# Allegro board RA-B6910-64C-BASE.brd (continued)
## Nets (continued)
PCIE_COFIG: R259.2 U9.C23
PCIE_REFCLK_N: U9.B25 YJ1.C8_1(TX3-_1)
PCIE_REFCLK_P: U9.B24 YJ1.C7_1(TX3+_1)
PSON1: C78.2 J8.A21(PSON) R2.2 R174.2
PSON2: C90.2 J9.A21(PSON) R1.2 R183.2
PULL_UP_3.3V_PWR1: D2.2(K2) R135.2 R235.1 R236.1
PULL_UP_3.3V_PWR2: D2.1(K1) R138.2 R237.1 R238.1
PWR1_OUTPUT_OK: R127.1 R178.1 U1.117(PT16A*)
PWR1_PRESENT#: C61.1 R131.2 R177.2 U1.114(PT16C)
PWR1_PSON: R2.1 U1.84(PR8C)
PWR1_RSVD: J8.B25(RESERVED)
PWR1_SCL: C73.2 J8.A20(SCL) R236.2 U8.14(SC4)
PWR1_SDA: C75.2 J8.A19(SDA) R235.2 U8.13(SD4)
PWR1_SMB_ALERT#: R135.1 R175.1 U1.112(PT17A*)
PWR2_OUTPUT_OK: R130.1 R187.1 U1.115(PT16B*)
PWR2_PRESENT#: C62.1 R133.2 R186.2 U1.113(PT16D)
PWR2_PSON: R1.1 U1.83(PR8D)
PWR2_RSVD: J9.B25(RESERVED)
PWR2_SCL: C85.2 J9.A20(SCL) R238.2 U8.16(SC5)
PWR2_SDA: C86.2 J9.A19(SDA) R237.2 U8.15(SD5)
PWR2_SMB_ALERT#: R138.1 R184.1 U1.111(PT17B*)
SCL_R: R300.1 R307.1 R309.1 U10.13(SCL_SLAVE)
SDA_R: R302.1 R308.1 R310.1 U10.14(SDA_SLAVE)
SLAVE_INT#: R267.2 R305.1 U10.15(\I\N\T\_\I\N\)
SMI_MDC: R81.2 R257.1 U9.D10
SMI_MDIO: R75.2 R256.1 U9.D7
SW_BOARD_INT#: C141.1 R112.1 U1.40(PB4C/CSSPIN) YJ1.A1_2(SIDEBAND7_2)
SW_BOARD_RST#: C140.1 R20.2 YJ1.D2_2(SIDEBAND6_2)
SW_DCDC_EN: C139.1 R140.2 YJ1.D1_2(SIDEBAND5_2)
SW_RESERVE1: R247.2 R318.1 R321.2
SW_RESERVE2: R248.2 R319.1 R323.2
TO_BMC_INT#: R121.2 R260.2 U9.C37
TO_CPU_INT#: R116.2 R258.2 U9.C20
UART0_SIN: J10.19 R275.1 U9.D1
UART0_SOUT: J10.17 R274.1 U9.B1
USB5V: C106.1 C107.1 C120.1 C121.1 C158.2 J10.21 J10.22 R205.1 U5.6(OUT)
USB_DM: J10.15 U9.D27
USB_DP: J10.14 U9.D28
USB_OC#: R125.2 U9.C29
USB_POWER_EN: R124.2 R209.2 U5.3(EN)
USB_POWER_OC#: R122.1 R208.2 U1.94(PR5A/DQS0)
USB_RX_N: R87.1 U9.A12
USB_RX_P: R69.1 U9.A11
USB_TX_N: U9.D25
USB_TX_P: U9.D24
VR_EN: J11.2 R145.2 R276.1 U9.D30
N17108255: R16.1 U1.125(PT12D/SDA/PCLKC0_0)
N17108932: R4.1 U1.137(PT10C/TDO)
N17120577: R17.1 U1.120(PT15C/JTAGENB)
N17132235: J7.1 R48.2
N17132359: J7.5 R49.2
N17132366: J7.9 R51.2
N17497473: J2.14 R98.1 R278.1 R311.1
N17497957: Q12.1(B) R101.2 R282.2
N17498397: J5.14 R104.1 R284.1 R313.1
N17503631: R54.1 U1.25(PL8C)
N17503838: R327.1 U1.32(PL10A)
N17504179: R6.1 U1.13(PL4C)
N17504817: R326.1 U1.19(PL5A/PCLKT3_1)
N17504991: R31.1 U1.5(PL3A/PCLKT3_2)
N17510509: R20.1 U1.105(PR2C)
N17540351: R89.1 U1.119(PT15D/PROGRAMN)
N17565545: R325.1 U1.3(PL2C/L_GPLLT_IN)
N17614810: J2.1 R96.2
N17614841: J4.1 R99.2
N17614872: J5.1 R102.2
N17614948: J4.3 R100.2
N17614979: J5.3 R103.2
N17615052: J2.3 R97.2
N17711157: J8.B19(A0) R172.1
N17711159: J8.B20(A1) R173.1
N17711235: J9.B22(\\C\R\_\B\U\S\) R185.1
N17711333: J9.B20(A1) R182.1
N17711335: J9.B19(A0) R181.1
N17711436: J8.B22(\\C\R\_\B\U\S\) R176.1
N17755002: J8.A25(PWOK) R178.2
N17758888: J8.A22(\\S\M\B\A\L\E\R\T\) R175.2
N17770839: J9.A25(PWOK) R187.2
N17770842: J9.A22(\\S\M\B\A\L\E\R\T\) R184.2
N17771627: J8.B24(PRESENT) R177.1
N17771650: J9.B24(PRESENT) R186.1
N17785334: C102.2 L2.2 U4.2(SW)
N17785336: R202.1 U4.6(VBST)
N17785348: C103.2 R204.2 R207.1 U4.4(VFB)
N17785528: C102.1 R202.2
N17786050: C91.2 L1.2 U3.2(SW)
N17786052: R192.1 U3.6(VBST)
N17786060: C92.2 R195.2 R201.2 U3.4(VFB)
N17786072: C91.1 R192.2
N17795988: C101.2 Q8.1(B) R199.2 R200.2
N17796014: Q8.3(C) R196.2 R197.1
N17796016: Q7.1(B) R197.2
N17801498: C105.1 L3.1 U5.1(IN)
N17801552: R208.1 U5.4(\\F\A\U\L\T\\)
N17801562: R206.1 U5.5(ILIM)
N17812600: J7.6 R171.1
N17823833: D3.1(ANODE) R194.2
N17824733: D1.1(ANODE) R119.2
N17825329: R124.1 U1.93(PR5B/DQS0N)
N17852949: R157.1 U1.12(PL4B)
N17861782: R220.1 R222.1 U7.7(A0)
N17861792: R223.1 R224.1 U7.6(A1)
N17861802: R225.1 R226.1 U7.5(A2)
N17861847: R219.2 U7.1(SDA)
N17862775: R221.2 U7.3(OS)
N17864736: R241.2 R244.2 U8.1(A0)
N17864738: R243.2 R246.2 U8.21(A2)
N17864740: R242.2 R245.2 U8.2(A1)
N17865867: R239.2 U8.23(SDA)
N17879948: R155.1 U2.7(2Y2)
N17880008: R146.1 U2.18(1Y0)
N17880012: R147.1 U2.16(1Y1)
N17880028: R148.1 U2.14(1Y2)
N17880056: R149.1 U2.12(1Y3)
N17880058: R151.1 U2.3(2Y0)
N17880102: R152.1 U2.5(2Y1)
N17880169: Q4.1(B) R153.2
N17880198: Q4.3(C) R150.2 U2.1(1\O\E\) U2.19(2\O\E\)
N17880220: R156.1 U2.9(2Y3)
N17885472: R125.1 U1.91(PR5D/PCLKC1_0)
N17885725: R116.1 U1.132(PT11B*)
N17885726: R121.1 U1.133(PT11A*)
N17894131: Q3.1(B) R145.1
N17894135: Q3.3(C) R143.1 U1.73(PR10D)
N17894645: R140.1 U1.78(PR9C)
N17894809: R128.1 U1.86(PR8A/DQS1)
N17894927: Q1.1(B) R117.1
N17894931: Q1.3(C) R113.1 U1.104(PR2D)
N17899016: R137.1 U1.60(PB15D)
N17899017: R136.1 U1.59(PB15C)
N17899018: R129.1 U1.54(PB11D)
N17899019: R139.1 U1.61(PB18A)
N17899020: R132.1 U1.57(PB15A)
N17899021: R134.1 U1.58(PB15B)
N17899022: R126.1 U1.52(PB11C)
N17905147: R75.1 R248.1 YJ1.C7_2(TX3+_2)
N17905148: R81.1 R247.1 YJ1.C8_2(TX3-_2)
N17912152: R321.1 U1.128(PT12A*/PCLKT0_1)
N17912154: R323.1 U1.127(PT12B*/PCLKC0_1)
N17933627: C150.2 Q10.1(B) R265.2 R266.2
N17933645: Q10.3(C) R262.2 R263.1
N17933655: Q9.1(B) R263.2
N17959753: R250.1 U1.55(PB11A/PCLKT2_1)
N17959756: R251.1 U1.56(PB11B/PCLKC2_1)
N17959810: R249.1 U1.41(PB4D)
N17988063: R291.2 U10.2(SDA_MST0)
N17988151: R301.2 U10.6(SDA_MST1)
N17988854: R290.2 U10.1(I\N\T\0\)
N17988900: R303.2 U10.7(I\N\T\1\)
N17997808: R267.1 U1.96(PR4C)
N17998511: R269.1 U1.48(PB9D)
N17998908: R272.1 U1.69(PB20B)
N18001007: R298.1 R299.1 U10.12(AD3)
N18001035: R295.1 R296.1 U10.11(AD2)
N18001064: R293.1 R294.1 U10.10(AD1)
N18001098: R289.1 R292.1 U10.9(AD0)
N18008506: J4.14 R101.1 R281.1 R312.1
N18009865: Q11.1(B) R98.2 R279.2
N18010804: Q13.1(B) R104.2 R285.2
N18021498: R58.1 U1.139(PT10A*)
N18217749: R314.1 U1.38(PB4A)
N18217752: R315.1 U1.39(PB4B)
N18217823: R316.1 U1.42(PB6A)
N18217826: R317.1 U1.43(PB6B)
N18217886: R322.1 U1.45(PB6D/SO/SPISO)
N18217888: R320.1 U1.44(PB6C/MCLK/CCLK)
N18217940: R324.1 U1.49(PB9A/PCLKT2_0)
N18225889: Q14.1(B) R331.2 R332.2
N18236302: Q15.1(B) R349.2 R350.2
N18236637: Q16.1(B) R354.2 R355.2
N18282960: J11.1 R356.1

Pads without a net: FD5 1; FD8 1; FD9 1; FD12 1; J1 11 12; J3 11 12; J7 7 8; J8 1 2; J9 1 2; U1 15 17 31 50 62 63 65 67 70 71 77 81 82 85 87 89 92 95 99 100 103 109 110 121 122 129 140; U8 10 11 17 18 19 20

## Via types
v1: diameter 0.457, hole 0.203, TOP to BOTTOM, 2121 vias
v2: diameter 0.457, hole 0.229, TOP to BOTTOM, 123 vias
v3: diameter 0.762, hole 0.381, TOP to BOTTOM, 144 vias
v4: diameter 0.813, hole 0.406, TOP to BOTTOM, 356 vias

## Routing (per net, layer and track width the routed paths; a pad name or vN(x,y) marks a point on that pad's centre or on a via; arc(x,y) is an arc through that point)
12V_LOAD_SHARE: length 403.3
  TOP w0.201: v2(74.62,103.69) 64.25,103.69 61.74,106.19 20.72,106.19 v1(11.42,115.5)
  SIG1 w0.15: v1(11.42,115.5) 11.42,117.78 10.54,118.66 10.54,127.18 J9.B23
  SIG2 w0.16: v2(74.62,103.69) 74.62,111.58 79.86,116.82 85.46,116.82 89.32,120.68 91.82,120.68 95.48,124.35 99.11,124.35 99.74,124.97 103.47,124.97 104.16,125.66 115.18,125.66 120.79,120.06 123.87,120.06 126.35,117.58 142.69,117.58 143.86,118.75 159.24,118.75 162.14,115.85 336.7,115.85 344.8,123.94 368.42,123.94 369.39,124.92 369.39,127.18 J8.B23
GND: length 1652.3
  TOP w0.229: U1.101 120.47,147.58 v1(120.13,147.25) ; v1(131.31,147.25) 130.97,147.58 U1.80 ; U1.116 116.02,143.1 v1(116.32,142.8) ; U1.134 v1(116.32,134.1) ; v1(130.47,128.35) 130.97,127.85 U1.29 ; U1.64 135.32,142.6 134.74,143.18 v1(134.74,143.56) ; U1.18 v1(125.47,125.91) ; U1.8 v1(120.47,128.32) ; U1.124 116.05,139.1 v1(116.32,139.37) ; v1(135.12,137.34) 135.36,137.1 U1.53 ; v1(134.99,133.4) 135.19,133.6 U1.46 ; U1.90 v1(125.97,147.25)
  TOP w0.254: U8.12 v1(92.17,151.95)
  TOP w0.305: U9.A25 v1(166.34,69.42) ; U9.A33 v1(166.34,59.26) ; U9.A30 v1(166.34,63.07) ; U9.B20 v1(165.07,77.04) ; U9.D32 v1(161.26,60.53) ; U9.D8 v1(161.26,92.28) ; U9.B23 v1(165.07,71.96) ; U9.C16 v1(162.53,82.12) ; v1(161.26,87.2) U9.D12 U9.C13 ; U9.D29 v1(161.26,64.34) ; U9.B32 v1(165.07,60.53) ; U9.A39 v1(166.34,51.64) ; U9.C10 v1(162.53,89.74) ; v1(166.34,93.55) U9.A7 v1(165.07,93.55) ; U9.A22 v1(166.34,73.23) ; U9.D20 v1(161.26,77.04) ; U2.10 v1(64.88,90.23) ; U9.A36 v1(166.34,55.45) ; U9.B39 v1(165.07,51.64) ; U9.A4 166.51,96.73 v1(166.74,96.96) ; U9.C33 v1(162.53,59.26) ; v1(165.07,88.47) U9.B11 v1(163.8,88.47) ; U9.D14 v1(162.53,83.39) U9.C15 ; U9.C39 v1(162.53,51.64) ; U9.B34 v1(165.07,57.99) ; v1(99.67,135.08) 99.89,135.3 U10.8 ; U9.B31 v1(165.07,61.8) ; U9.C30 v1(162.53,63.07) ; U9.B29 v1(165.07,64.34) ; U9.D39 v1(161.26,51.64) ; v1(165.07,94.82) U9.B6 v1(163.8,94.82) ; U9.C28 v1(162.53,65.61) ; v1(165.07,96.09) U9.B5 v1(163.8,96.09) ; v1(162.53,70.69) U9.C24 v1(163.8,70.69) ; U9.D35 v1(161.26,56.72) ; U9.A27 v1(165.07,68.15) U9.B26 v1(163.8,69.42) U9.C25 ; v1(165.07,91.01) U9.B9 v1(163.8,91.01) ; U9.D31 v1(161.26,61.8) ; U9.C7 v1(163.8,92.28) U9.B8 v1(165.07,92.28) ; U9.B17 v1(165.07,80.85) ; U9.D26 v1(162.53,68.15) U9.C27 ; U9.D37 v1(162.53,55.45) U9.C36 ; U9.A24 v1(166.34,70.69) ; v1(162.53,78.31) U9.C19 v1(163.8,78.31) ; v1(163.8,74.5) U9.C21 v1(162.53,74.5) ; U9.A13 v1(166.48,85.3) ; U9.A15 v1(165.12,83.34) U9.B14 ; U9.D2 v1(161.26,99.9) ; v1(165.07,87.2) U9.B12 v1(163.8,87.2) ; U9.A28 v1(166.34,65.61) ; U9.A18 v1(166.34,79.58) ; v1(163.8,99.9) U9.B2 v1(165.07,99.9) ; v1(163.8,79.58) U9.C18 v1(162.58,79.53) U9.D17 ; v1(163.75,73.26) 163.17,73.84 U9.C22 v1(162.53,73.23) U9.D23 ; v1(163.8,98.63) U9.B3 v1(165.07,98.63) ; U9.B35 v1(165.07,56.72) ; U9.D9 v1(161.26,91.01) ; U9.A19 v1(166.34,78.31) ; U9.D11 v1(161.26,88.47) ; U9.A16 v1(165.07,82.12) ; U9.C4 v1(162.53,97.36) ; U9.D34 v1(161.26,57.99) ; U9.A10 v1(166.34,89.74) ; U9.D6 v1(161.26,94.82) ; U9.A21 v1(166.34,74.5) ; U9.D3 v1(161.26,98.63) ; U9.D5 v1(161.26,96.09) ; v1(162.55,101.15) U9.C1
  TOP w0.381: v1(369.24,117.96) 369.24,118.64 C77.1 370.13,118.51 v1(370.13,117.96) ; v1(138.67,153.98) 139,153.65 Q3.2 ; U5.2 392.93,29.77 v1(393.18,30.03) ; 10.66,42.47 C131.1 11.01,43.51 11.67,42.85 ; C129.2 v1(379.72,14.7) ; v1(120.54,155.53) 120.23,155.53 119.82,155.93 Q1.2 ; Q13.2 v1(103.98,154.93) ; R127.2 v1(107.69,143.06) ; C134.2 v1(54.5,87.94) ; C73.1 v1(374.83,119.35) ; C17.2 135.24,123.14 135.78,122.61 v1(136.39,122.61) C5.1 ; R282.1 238.12,167.19 v1(238.5,167.56) ; C4.1 140.45,143.31 v1(140.71,143.56) ; R209.1 396.48,30.79 v1(397.37,31.68) ; v1(75.43,100.82) 75.73,100.51 C146.2 ; v1(98.16,140.61) 98.16,140.77 97.91,141.02 R246.1 ; C155.1 C154.1 90.46,129.72 90.15,130.03 v1(89.93,130.03) ; v1(328.41,168.96) 328.18,169.19 R332.1 ; v1(13.12,118.61) 13.6,118.61 C89.1 13.8,119.5 v1(13.12,119.5) ; Q10.2 v1(390.71,45.59) ; C65.2 v1(110.35,141.91) ; C138.2 v1(69.56,89.46) ; v1(118.87,154.84) 118.76,154.84 118.76,154.84 C140.2 ; C136.2 v1(65.65,93.78) ; C8.1 v1(127.24,152.83) ; v1(12.19,118.66) 12.12,118.73 C87.1 ; R180.2 v1(8.5,121.9) ; C149.2 144.42,80.08 v1(144.34,80.01) ; Q4.2 v1(50.35,90.16) ; C78.1 v1(372.54,119.35) ; C10.1 v1(36.69,90.1) ; C19.1 C22.1 v1(110.35,127.94) ; U7.4 v1(147.75,169.12) ; R200.1 v1(413.76,53.9) ; Q16.2 v1(137.53,160.78) ; R355.1 v1(134.48,165.76) ; C147.2 C148.2 75.78,101.53 v1(75.53,101.78) ; v1(102.99,156.82) 102.56,157.25 R285.1 ; Q8.2 409.75,53.01 v1(409.5,53.27) ; C21.1 v1(110.35,133.02) ; v1(124.6,122.68) 124.58,122.71 C48.1 ; C18.2 v1(140.71,149.15) ; C67.1 v1(362.25,118.46) ; R266.1 v1(387.59,45.27) ; R244.1 v1(101.97,155.63) ; C158.1 v1(385.43,26.85) ; C135.2 v1(69.56,85.91) ; C116.2 v1(156.49,173.71) ; C51.1 v1(119.75,122.61) ; C68.1 v1(363.78,118.46) ; Q12.2 v1(233.92,169.02) ; R226.2 v1(158.08,169.22) ; R130.2 v1(110.35,143.06) ; R276.2 v1(144.41,68.63) ; R279.1 137.66,122.48 v1(137.53,122.61) C20.1 ; v1(144.64,125.53) 144.26,125.91 C141.2 ; v4(23.29,117.45) X21.1 ; R295.2 88.89,135.82 v1(87.87,134.8) 88,134.67 R298.2 ; C3.1 v1(140.71,147.12) ; v1(385.43,27.99) R205.2 ; Q15.2 v1(238.3,171.94) ; C7.1 v1(140.71,148.14) ; v1(75.2,99.95) 75.66,99.49 C144.2 C145.2 ; v1(384.65,29.39) R206.2 ; R173.2 v1(373.68,119.35) ; v1(143.63,87.24) R69.2 R87.2 ; C75.1 v1(377.11,119.35) ; C64.2 110.79,139.5 v1(110.35,139.93) ; R289.2 89.02,138.48 v1(88,137.47) 88.38,137.09 R293.2 ; C62.2 v1(110.35,145.47) ; Q11.2 v1(134.67,121.14) ; C61.2 v1(110.35,144.2) ; C130.2 v1(377.43,14.7) ; C2.1 v1(130.9,152.17) ; v1(3.35,118.67) C79.1 C81.1 ; R183.1 v1(17.2,116.69) ; v1(36.69,95.18) R171.2 ; v1(116.32,150.42) 115.81,150.93 C156.2 ; C66.2 113.78,152.87 v1(113.91,153) ; Q7.2 v1(407.86,58.29) ; C6.1 v1(110.35,128.96) ; R172.2 v1(375.97,119.35) ; R174.1 v1(371.4,119.35) ; C23.1 v1(140.71,134.93) ; C50.1 v1(131.05,122.74) ; C16.2 v1(140.71,128.83) ; R222.2 v1(156.36,172.57) ; v1(68.7,84.13) 68.32,84.51 R253.1 ; Q14.2 v1(333.17,169.15) ; C150.1 v1(388.74,45.27) ; R198.2 v1(406.01,57.84) ; C143.2 C142.2 76.6,95.21 v1(77.11,94.69) ; R350.1 233.31,171.86 v1(233.54,171.63) ; R182.2 v1(18.34,119.35) ; C74.1 v1(367.59,118.34) ; C157.1 C49.1 v1(140.58,127.82) ; R45.2 v1(34.15,87.81) ; C86.1 v1(22.15,119.35) ; C9.1 v1(120.39,153.09) ; 49.77,42.85 48.99,43.64 C151.1 48.63,42.34 ; C63.1 v1(54.5,83.11) ; R223.2 v1(156.36,170.53) ; C137.2 v1(65.65,97.84) ; C139.2 v1(134.36,151.21) ; R259.1 v1(144.42,76.51) ; C1.1 v1(114.8,152.96) ; R181.2 v1(21.01,119.35) ; C101.1 v1(413.76,51.11) ; R201.1 v1(394.73,48.06) ; R264.2 v1(394.2,42.98) ; D1.2 v1(113.43,155.37) ; R245.1 v1(98.92,155.63) ; C117.1 v1(99.94,140.64) ; R109.2 v1(116.96,152.96) ; C85.1 v1(19.99,119.35) ; C90.1 v1(17.2,119.35)
  TOP w0.508: U4.1 v1(400.1,56.12) ; v1(410.33,47.68) 410.45,47.55 C97.2 ; v1(93.84,146.36) 99.43,146.36 100.7,145.09 100.7,141.91 v1(100.7,141.91) 100.7,140.28 100.2,139.78 98.96,139.78 96.24,137.06 v1(96.24,131.37) 96.24,123.51 v1(101.6,118.15) 101.6,118.13 104.11,115.62 v1(104.13,115.62) 104.13,115.37 105.02,114.48 106.54,114.48 107.43,115.37 v1(107.43,115.62) 107.43,115.88 v1(104.89,118.42) 98.67,124.64 v1(98.67,125.5) v1(98.67,133.1) 98.67,136.05 99.96,137.34 101.34,137.34 103.24,139.25 103.24,146.36 v1(102.99,146.61) 100.45,149.15 92.83,149.15 90.54,146.87 v1(90.54,142.67) ; R207.2 406.39,51.74 v1(406.77,51.36) ; U3.1 400.36,41.9 v1(399.91,41.46) ; C99.2 414.52,46.92 v1(414.39,47.04) ; 397.25,50.09 397.27,50.12 C108.2 ; C98.2 411.98,47.55 ; C100.1 413.37,47.55 ; C113.2 v1(384.55,55.17) ; Q9.2 v1(393.69,39.42) ; C94.2 v1(399.15,45.77) ; C114.1 v1(384.55,54.03) ; X23.1 v1(415.72,49.27) ; X25.1 v1(404.36,30.15) ; D3.2 v1(416.42,48.31)
  GND1 w0.508: J9.A7 52.46,127.07 ; J9.A7 53.62,125.91 ; J9.A7 51.3,125.91 ; J9.A7 52.46,124.76 ; J4.9 208.34,168.41 ; J4.9 207.28,167.35 ; J4.9 206.22,168.41 ; J2.10 306.18,168.41 ; J2.10 305.12,167.35 ; J2.10 304.06,168.41 ; J8.B9 403.68,129.61 ; J8.B9 404.84,128.45 ; J8.B9 403.68,127.3 ; 113.46,168.41 J5.10 ; J5.10 115.58,168.41 ; J5.10 114.52,167.35 ; J9.A9 47.38,127.07 ; J9.A9 47.38,124.76 ; J9.A9 48.54,125.91 ; 47.38,127.3 J9.B9 ; J9.B9 47.38,129.61 ; J9.B9 48.54,128.45 ; J2.9 303.64,168.41 ; J2.9 301.52,168.41 ; J2.9 302.58,167.35 ; 61.46,125.91 J9.A3 ; J9.A3 63.78,125.91 ; J9.A3 62.62,124.76 ; J9.A3 62.62,127.07 ; J9.B2 65.16,129.61 ; J9.B2 66.32,128.45 ; J9.B2 65.16,127.3 ; J9.B2 64,128.45 ; 382.44,5.75 J10.25 ; J10.25 383.35,4.84 ; J10.25 383.35,6.66 ; J9.A23 11.82,127.07 ; J9.A23 12.98,125.91 ; J9.A23 11.82,124.76 ; J4.11 213.42,168.41 ; J4.11 212.36,169.47 ; J4.11 211.3,168.41 ; J4.11 212.36,167.35 ; J8.B2 422.62,128.45 ; J8.B2 420.3,128.45 ; J8.B2 421.46,127.3 ; J8.B2 421.46,129.61 ; J9.A6 55,127.07 ; J9.A6 56.16,125.91 ; J9.A6 55,124.76 ; J9.A6 53.84,125.91 ; J9.A8 49.92,127.07 ; J9.A8 51.08,125.91 ; J9.A8 48.76,125.91 ; J9.A8 49.92,124.76 ; 66.54,128.45 J9.B1 ; J9.B1 68.86,128.45 ; J9.B1 67.7,127.3 ; J9.B1 67.7,129.61 ; 422.84,125.91 J8.A1 ; J8.A1 424,127.07 ; J8.A1 424,124.76 ; J8.A1 425.16,125.91 ; J9.A4 61.24,125.91 ; J9.A4 58.92,125.91 ; J9.A4 60.08,124.76 ; J9.A4 60.08,127.07 ; J7.10 26.62,98.73 ; J7.10 25.64,99.71 ; J7.10 24.67,98.73 ; J7.10 25.64,97.75 ; 49.92,127.3 J9.B8 ; J9.B8 49.92,129.61 ; J9.B8 51.08,128.45 ; J9.B8 48.76,128.45 ; J9.A5 57.54,127.07 ; J9.A5 58.7,125.91 ; J9.A5 57.54,124.76 ; J9.A5 56.38,125.91 ; J2.11 308.72,168.41 ; J2.11 306.6,168.41 ; J2.11 307.66,167.35 ; J2.11 307.66,169.47 ; 64,125.91 J9.A2 ; J9.A2 65.16,124.76 ; J9.A2 66.32,125.91 ; J9.A2 65.16,127.07 ; 53.84,128.45 J9.B6 ; J9.B6 56.16,128.45 ; J9.B6 55,127.3 ; 418.92,124.76 J8.A3 ; J8.A3 418.92,127.07 ; J8.A3 420.08,125.91 ; J8.A3 417.76,125.91 ; J9.A1 67.7,127.07 ; J9.A1 66.54,125.91 ; J9.A1 67.7,124.76 ; J9.A1 68.86,125.91 ; 421.46,124.76 J8.A2 ; J8.A2 420.3,125.91 ; J8.A2 422.62,125.91 ; J8.A2 421.46,127.07 ; 412.68,128.45 J8.B5 ; J8.B5 415,128.45 ; J8.B5 413.84,127.3 ; 117.06,167.35 J5.11 ; J5.11 118.12,168.41 ; J5.11 116,168.41 ; J5.11 117.06,169.47 ; J8.B1 425.16,128.45 ; J8.B1 424,127.3 ; J8.B1 424,129.61 ; J8.B1 422.84,128.45 ; J10.13 395.35,6.66 ; J10.13 395.35,4.84 ; J10.13 394.44,5.75 ; 62.62,127.3 J9.B3 ; J9.B3 61.46,128.45 ; J9.B3 63.78,128.45 ; 403.68,124.76 J8.A9 ; J8.A9 404.84,125.91 ; J8.A9 403.68,127.07 ; J8.A8 406.22,127.07 ; J8.A8 406.22,124.76 ; J8.A8 407.38,125.91 ; J8.A8 405.06,125.91 ; 385.35,4.84 J10.23 385.35,6.66 ; 25.64,87.59 J7.2 ; J7.2 26.62,88.57 ; J7.2 25.64,89.55 ; J7.2 24.67,88.57 ; 52.46,127.3 J9.B7 ; J9.B7 52.46,129.61 ; J9.B7 53.62,128.45 ; J9.B7 51.3,128.45 ; 416.38,127.3 J8.B4 ; J8.B4 415.22,128.45 ; J8.B4 417.54,128.45 ; J8.B4 416.38,129.61 ; 418.92,127.3 J8.B3 ; J8.B3 417.76,128.45 ; J8.B3 418.92,129.61 ; J8.B3 420.08,128.45 ; J8.A4 416.38,127.07 ; J8.A4 415.22,125.91 ; J8.A4 416.38,124.76 ; J8.A4 417.54,125.91 ; 208.76,168.41 J4.10 ; J4.10 209.82,167.35 ; J4.10 210.88,168.41 ; 412.68,125.91 J8.A5 ; J8.A5 413.84,127.07 ; J8.A5 415,125.91 ; J8.A5 413.84,124.76 ; J9.B4 61.24,128.45 ; J9.B4 58.92,128.45 ; J9.B4 60.08,127.3 ; J8.A7 409.92,125.91 ; J8.A7 407.6,125.91 ; J8.A7 408.76,124.76 ; J8.A7 408.76,127.07 ; J10.4 405.35,2.62 ; 56.38,128.45 J9.B5 ; J9.B5 58.7,128.45 ; J9.B5 57.54,127.3 ; 407.35,6.66 J10.1 408.26,5.75 ; 410.14,128.45 J8.B6 ; J8.B6 411.3,127.3 ; J8.B6 412.46,128.45 ; J10.10 399.35,2.65 ; 393.35,2.84 J10.16 ; J10.16 394.26,3.75 ; J10.16 393.35,4.66 ; J8.B8 407.38,128.45 ; J8.B8 406.22,127.3 ; J8.B8 405.06,128.45 ; 111.98,167.35 J5.9 ; J5.9 113.04,168.41 ; J5.9 110.92,168.41 ; 411.3,124.76 J8.A6 ; J8.A6 410.14,125.91 ; J8.A6 411.3,127.07 ; J8.A6 412.46,125.91 ; 391.35,2.84 J10.18 391.35,4.66 ; J8.B7 409.92,128.45 ; J8.B7 407.6,128.45 ; J8.B7 408.76,127.3 ; 389.35,4.66 J10.20 389.35,2.84 ; J10.7 401.35,6.87
  SIG1 w0.508: v1(110.73,115.62) v1(107.43,115.62) 107.43,115.37 106.54,114.48 105.02,114.48 104.13,115.37 v1(104.13,115.62) 104.13,115.76 106.15,117.78 v1(107.18,117.78) 111.88,117.78 112.77,116.89 v1(123.32,116.89) 127.58,116.89 v1(127.75,116.72) 128.13,116.34 128.13,114.61 127.75,114.23 112.13,114.23 v1(110.73,115.62)
  GND2 w0.508: 56.38,125.91 J9.A5 ; J9.A5 57.54,127.07 ; J9.A5 57.54,124.76 ; J9.A5 58.7,125.91 ; 305.12,167.35 J2.10 ; J2.10 304.06,168.41 ; J2.10 306.18,168.41 ; 58.92,125.91 J9.A4 ; J9.A4 60.08,124.76 ; J9.A4 60.08,127.07 ; J9.A4 61.24,125.91 ; 15.76,62.34 J3.4 ; J3.4 14.24,63.85 ; J3.4 17.27,63.85 ; J3.4 15.76,65.36 ; J8.A7 409.92,125.91 ; J8.A7 408.76,124.76 ; J8.A7 408.76,127.07 ; J8.A7 407.6,125.91 ; J8.A5 415,125.91 ; J8.A5 413.84,124.76 ; J8.A5 413.84,127.07 ; J8.A5 412.68,125.91 ; J9.B2 65.16,129.61 ; J9.B2 65.16,127.3 ; J9.B2 66.32,128.45 ; J9.B2 64,128.45 ; 394.44,5.75 J10.13 ; J10.13 395.35,6.66 ; J10.13 395.35,4.84 ; J1.4 51.76,65.36 ; J1.4 50.24,63.85 ; J1.4 53.27,63.85 ; J1.4 51.76,62.34 ; J10.16 394.26,3.75 ; J10.16 393.35,2.84 ; J10.16 393.35,4.66 ; 113.46,168.41 J5.10 ; J5.10 114.52,167.35 ; J5.10 115.58,168.41 ; J8.A2 422.62,125.91 ; J8.A2 420.3,125.91 ; J8.A2 421.46,124.76 ; J8.A2 421.46,127.07 ; 51.3,125.91 J9.A7 ; J9.A7 53.62,125.91 ; J9.A7 52.46,127.07 ; J9.A7 52.46,124.76 ; 405.06,125.91 J8.A8 ; J8.A8 406.22,127.07 ; J8.A8 406.22,124.76 ; J8.A8 407.38,125.91 ; J9.A9 48.54,125.91 ; J9.A9 47.38,127.07 ; J9.A9 47.38,124.76 ; J8.B6 412.46,128.45 ; J8.B6 410.14,128.45 ; J8.B6 411.3,127.3 ; J9.A23 11.82,127.07 ; J9.A23 12.98,125.91 ; J9.A23 11.82,124.76 ; 55,124.76 J9.A6 ; J9.A6 53.84,125.91 ; J9.A6 56.16,125.91 ; J9.A6 55,127.07 ; 62.62,127.3 J9.B3 ; J9.B3 63.78,128.45 ; J9.B3 61.46,128.45 ; J2.11 308.72,168.41 ; J2.11 307.66,169.47 ; J2.11 307.66,167.35 ; J2.11 306.6,168.41 ; 405.06,128.45 J8.B8 ; J8.B8 406.22,127.3 ; J8.B8 407.38,128.45 ; 211.3,168.41 J4.11 ; J4.11 213.42,168.41 ; J4.11 212.36,167.35 ; J4.11 212.36,169.47 ; J8.A9 403.68,127.07 ; J8.A9 404.84,125.91 ; J8.A9 403.68,124.76 ; J3.5 13.07,63.85 ; J3.5 11.55,62.34 ; J3.5 11.55,65.36 ; J3.5 10.04,63.85 ; J9.A1 68.86,125.91 ; J9.A1 67.7,124.76 ; J9.A1 67.7,127.07 ; J9.A1 66.54,125.91 ; 415.22,128.45 J8.B4 ; J8.B4 416.38,127.3 ; J8.B4 416.38,129.61 ; J8.B4 417.54,128.45 ; 382.44,5.75 J10.25 ; J10.25 383.35,4.84 ; J10.25 383.35,6.66 ; J8.B9 404.84,128.45 ; J8.B9 403.68,127.3 ; J8.B9 403.68,129.61 ; 24.16,62.34 J3.2 ; J3.2 25.67,63.85 ; J3.2 22.64,63.85 ; J3.2 24.16,65.36 ; J9.B5 58.7,128.45 ; J9.B5 56.38,128.45 ; J9.B5 57.54,127.3 ; J3.1 29.87,63.85 ; J3.1 26.84,63.85 ; J3.1 28.36,62.34 ; J3.1 28.36,65.36 ; 64.35,62.34 J1.1 ; J1.1 64.35,65.36 ; J1.1 65.87,63.85 ; J1.1 62.84,63.85 ; J8.B7 409.92,128.45 ; J8.B7 407.6,128.45 ; J8.B7 408.76,127.3 ; J8.B2 421.46,129.61 ; J8.B2 420.3,128.45 ; J8.B2 422.62,128.45 ; J8.B2 421.46,127.3 ; J7.2 25.64,89.55 ; J7.2 24.67,88.57 ; J7.2 26.62,88.57 ; J7.2 25.64,87.59 ; 117.06,167.35 J5.11 ; J5.11 117.06,169.47 ; J5.11 118.12,168.41 ; J5.11 116,168.41 ; 424,124.76 J8.A1 ; J8.A1 425.16,125.91 ; J8.A1 422.84,125.91 ; J8.A1 424,127.07 ; 54.44,63.85 J1.3 ; J1.3 57.47,63.85 ; J1.3 55.95,65.36 ; J1.3 55.95,62.34 ; J1.2 60.16,65.36 ; J1.2 61.67,63.85 ; J1.2 58.64,63.85 ; J1.2 60.16,62.34 ; J10.4 405.35,2.49 ; J1.5 47.55,65.36 ; J1.5 46.04,63.85 ; J1.5 49.07,63.85 ; J1.5 47.55,62.34 ; 52.46,127.3 J9.B7 ; J9.B7 53.62,128.45 ; J9.B7 51.3,128.45 ; J9.B7 52.46,129.61 ; J9.A2 66.32,125.91 ; J9.A2 65.16,124.76 ; J9.A2 65.16,127.07 ; J9.A2 64,125.91 ; 25.64,97.75 J7.10 ; J7.10 26.62,98.73 ; J7.10 25.64,99.71 ; J7.10 24.67,98.73 ; 67.7,127.3 J9.B1 ; J9.B1 66.54,128.45 ; J9.B1 68.86,128.45 ; J9.B1 67.7,129.61 ; 49.92,124.76 J9.A8 ; J9.A8 49.92,127.07 ; J9.A8 48.76,125.91 ; J9.A8 51.08,125.91 ; 368.12,124.76 J8.A23 ; J8.A23 369.28,125.91 ; J8.A23 368.12,127.07 ; J8.B1 424,129.61 ; J8.B1 422.84,128.45 ; J8.B1 424,127.3 ; J8.B1 425.16,128.45 ; 209.82,167.35 J4.10 ; J4.10 210.88,168.41 ; J4.10 208.76,168.41 ; 47.38,127.3 J9.B9 ; J9.B9 48.54,128.45 ; J9.B9 47.38,129.61 ; 413.84,127.3 J8.B5 ; J8.B5 415,128.45 ; J8.B5 412.68,128.45 ; 111.98,167.35 J5.9 ; J5.9 113.04,168.41 ; J5.9 110.92,168.41 ; 55,127.3 J9.B6 ; J9.B6 56.16,128.45 ; J9.B6 53.84,128.45 ; J8.A6 411.3,127.07 ; J8.A6 410.14,125.91 ; J8.A6 412.46,125.91 ; J8.A6 411.3,124.76 ; J9.B4 61.24,128.45 ; J9.B4 58.92,128.45 ; J9.B4 60.08,127.3 ; J8.A3 418.92,127.07 ; J8.A3 417.76,125.91 ; J8.A3 418.92,124.76 ; J8.A3 420.08,125.91 ; J9.B8 51.08,128.45 ; J9.B8 48.76,128.45 ; J9.B8 49.92,129.61 ; J9.B8 49.92,127.3 ; 391.35,2.84 J10.18 391.35,4.66 ; J4.9 208.34,168.41 ; J4.9 206.22,168.41 ; J4.9 207.28,167.35 ; J8.B3 420.08,128.45 ; J8.B3 418.92,129.61 ; J8.B3 417.76,128.45 ; J8.B3 418.92,127.3 ; J8.A4 417.54,125.91 ; J8.A4 416.38,124.76 ; J8.A4 416.38,127.07 ; J8.A4 415.22,125.91 ; 62.62,124.76 J9.A3 ; J9.A3 63.78,125.91 ; J9.A3 62.62,127.07 ; J9.A3 61.46,125.91 ; 19.96,62.34 J3.3 ; J3.3 19.96,65.36 ; J3.3 21.47,63.85 ; J3.3 18.44,63.85 ; 385.35,4.84 J10.23 385.35,6.66 ; J2.9 303.64,168.41 ; J2.9 302.58,167.35 ; J2.9 301.52,168.41 ; 408.26,5.75 J10.1 407.35,6.66 ; J10.10 399.35,2.79 ; 389.35,2.84 J10.20 389.35,4.66 ; J10.7 401.35,7
  SIG2 w0.508: v1(358.85,123.04) v1(347.08,123.04) 345.1,123.04 v1(339.33,117.27) 337.05,114.99 v1(330.44,114.99) v1(268.47,114.99) v1(252.08,114.99) v1(237.35,114.99) v1(220.97,114.99) v1(206.36,114.99) v1(191.25,114.99) v1(180.58,114.99) 161.81,114.99 v1(158.89,117.91) 144.23,117.91 143.04,116.72 v1(135.75,116.72) v1(127.75,116.72) 126.78,116.72 126.23,116.17 126.23,114.73 127.04,113.92 v1(134.74,113.92) 144.2,113.92 145.77,115.5 v1(157.98,115.5) 161.28,112.19 v1(180.84,112.19) v1(191.25,112.19) v1(206.36,112.19) v1(221.22,112.19) v1(237.61,112.19) v1(252.08,112.19) v1(268.34,112.19) v1(330.44,112.19) 338.44,112.19 v1(341.75,115.5) v1(346.95,120.7) v1(359.02,120.7)
  BOTTOM w0.508: J9.A5 57.54,127.07 ; J9.A5 57.54,124.76 ; J9.A5 56.38,125.91 ; J9.A5 58.7,125.91 ; J3.4 17.27,63.85 ; J3.4 15.76,62.34 ; J3.4 14.24,63.85 ; J3.4 15.76,65.36 ; 418.92,127.3 J8.B3 ; J8.B3 418.92,129.61 ; J8.B3 417.76,128.45 ; J8.B3 420.08,128.45 ; 24.67,88.57 J7.2 ; J7.2 25.64,89.55 ; J7.2 26.62,88.57 ; J7.2 25.64,87.59 ; 67.7,127.3 J9.B1 ; J9.B1 67.7,129.61 ; J9.B1 66.54,128.45 ; J9.B1 68.86,128.45 ; J3.2 24.16,65.36 ; J3.2 25.67,63.85 ; J3.2 24.16,62.34 ; J3.2 22.64,63.85 ; 393.35,2.84 J10.16 ; J10.16 394.26,3.75 ; J10.16 393.35,4.66 ; 65.16,127.3 J9.B2 ; J9.B2 64,128.45 ; J9.B2 66.32,128.45 ; J9.B2 65.16,129.61 ; 406.22,124.76 J8.A8 ; J8.A8 406.22,127.07 ; J8.A8 407.38,125.91 ; J8.A8 405.06,125.91 ; 207.28,167.35 J4.9 208.34,168.41 ; 395.35,4.84 J10.13 ; J10.13 394.44,5.75 ; J10.13 395.35,6.66 ; J5.10 115.58,168.41 ; J5.10 113.46,168.41 ; J5.10 114.52,167.35 ; 307.66,167.35 J2.11 ; J2.11 307.66,169.47 ; J2.11 308.72,168.41 ; J2.11 306.6,168.41 ; 55,124.76 J9.A6 ; J9.A6 53.84,125.91 ; J9.A6 55,127.07 ; J9.A6 56.16,125.91 ; J9.B8 51.08,128.45 ; J9.B8 49.92,129.61 ; J9.B8 49.92,127.3 ; J9.B8 48.76,128.45 ; J1.2 61.67,63.85 ; J1.2 58.64,63.85 ; J1.2 60.16,65.36 ; J1.2 60.16,62.34 ; 418.92,124.76 J8.A3 ; J8.A3 420.08,125.91 ; J8.A3 417.76,125.91 ; J8.A3 418.92,127.07 ; 28.36,62.34 J3.1 ; J3.1 29.87,63.85 ; J3.1 26.84,63.85 ; J3.1 28.36,65.36 ; 64.35,62.34 J1.1 ; J1.1 64.35,65.36 ; J1.1 65.87,63.85 ; J1.1 62.84,63.85 ; 420.3,125.91 J8.A2 ; J8.A2 422.62,125.91 ; J8.A2 421.46,127.07 ; J8.A2 421.46,124.76 ; 403.68,127.3 J8.B9 404.84,128.45 ; 61.46,125.91 J9.A3 ; J9.A3 62.62,124.76 ; J9.A3 63.78,125.91 ; J9.A3 62.62,127.07 ; 405.06,128.45 J8.B8 ; J8.B8 407.38,128.45 ; J8.B8 406.22,127.3 ; J10.4 405.35,2.62 ; J7.10 26.62,98.73 ; J7.10 24.67,98.73 ; J7.10 25.64,99.71 ; J7.10 25.64,97.75 ; J3.3 19.96,65.36 ; J3.3 19.96,62.34 ; J3.3 21.47,63.85 ; J3.3 18.44,63.85 ; 383.35,4.84 J10.25 383.35,6.66 ; 113.04,168.41 J5.9 111.98,167.35 ; J9.B7 52.46,129.61 ; J9.B7 53.62,128.45 ; J9.B7 52.46,127.3 ; J9.B7 51.3,128.45 ; 407.6,125.91 J8.A7 ; J8.A7 409.92,125.91 ; J8.A7 408.76,124.76 ; J8.A7 408.76,127.07 ; J9.B6 56.16,128.45 ; J9.B6 55,127.3 ; J9.B6 53.84,128.45 ; 60.08,127.3 J9.B4 ; J9.B4 61.24,128.45 ; J9.B4 58.92,128.45 ; J10.7 401.35,7 ; J2.10 306.18,168.41 ; J2.10 305.12,167.35 ; J2.10 304.06,168.41 ; 410.14,125.91 J8.A6 ; J8.A6 411.3,127.07 ; J8.A6 412.46,125.91 ; J8.A6 411.3,124.76 ; J3.5 13.07,63.85 ; J3.5 11.55,65.36 ; J3.5 11.55,62.34 ; J3.5 10.04,63.85 ; 408.26,5.75 J10.1 407.35,6.66 ; 391.35,4.66 J10.18 391.35,2.84 ; J9.B9 47.38,129.61 ; J9.B9 48.54,128.45 ; J9.B9 47.38,127.3 ; 64,125.91 J9.A2 ; J9.A2 65.16,124.76 ; J9.A2 65.16,127.07 ; J9.A2 66.32,125.91 ; 212.36,167.35 J4.11 ; J4.11 213.42,168.41 ; J4.11 211.3,168.41 ; J4.11 212.36,169.47 ; 422.84,128.45 J8.B1 ; J8.B1 424,129.61 ; J8.B1 425.16,128.45 ; J8.B1 424,127.3 ; 302.58,167.35 J2.9 303.64,168.41 ; 61.46,128.45 J9.B3 ; J9.B3 62.62,127.3 ; J9.B3 63.78,128.45 ; 51.76,62.34 J1.4 ; J1.4 50.24,63.85 ; J1.4 53.27,63.85 ; J1.4 51.76,65.36 ; J9.A23 11.82,127.07 ; J9.A23 11.82,124.76 ; J9.A23 12.98,125.91 ; 407.6,128.45 J8.B7 ; J8.B7 409.92,128.45 ; J8.B7 408.76,127.3 ; J5.11 117.06,169.47 ; J5.11 118.12,168.41 ; J5.11 117.06,167.35 ; J5.11 116,168.41 ; J9.A1 67.7,127.07 ; J9.A1 67.7,124.76 ; J9.A1 66.54,125.91 ; J9.A1 68.86,125.91 ; 46.04,63.85 J1.5 ; J1.5 47.55,62.34 ; J1.5 47.55,65.36 ; J1.5 49.07,63.85 ; 51.3,125.91 J9.A7 ; J9.A7 53.62,125.91 ; J9.A7 52.46,124.76 ; J9.A7 52.46,127.07 ; J1.3 57.47,63.85 ; J1.3 55.95,62.34 ; J1.3 55.95,65.36 ; J1.3 54.44,63.85 ; 416.38,124.76 J8.A4 ; J8.A4 416.38,127.07 ; J8.A4 417.54,125.91 ; J8.A4 415.22,125.91 ; 368.12,124.76 J8.A23 ; J8.A23 368.12,127.07 ; J8.A23 369.28,125.91 ; J9.A8 51.08,125.91 ; J9.A8 49.92,127.07 ; J9.A8 48.76,125.91 ; J9.A8 49.92,124.76 ; 389.35,4.66 J10.20 389.35,2.84 ; 385.35,4.84 J10.23 385.35,6.66 ; 411.3,127.3 J8.B6 ; J8.B6 412.46,128.45 ; J8.B6 410.14,128.45 ; J8.B5 415,128.45 ; J8.B5 412.68,128.45 ; J8.B5 413.84,127.3 ; J9.A9 48.54,125.91 ; J9.A9 47.38,124.76 ; J9.A9 47.38,127.07 ; 421.46,127.3 J8.B2 ; J8.B2 422.62,128.45 ; J8.B2 420.3,128.45 ; J8.B2 421.46,129.61 ; J8.A1 424,127.07 ; J8.A1 425.16,125.91 ; J8.A1 422.84,125.91 ; J8.A1 424,124.76 ; J8.B4 417.54,128.45 ; J8.B4 416.38,129.61 ; J8.B4 416.38,127.3 ; J8.B4 415.22,128.45 ; J9.A4 60.08,127.07 ; J9.A4 61.24,125.91 ; J9.A4 60.08,124.76 ; J9.A4 58.92,125.91 ; J8.A9 404.84,125.91 ; J8.A9 403.68,127.07 ; J8.A9 403.68,124.76 ; J8.A5 415,125.91 ; J8.A5 412.68,125.91 ; J8.A5 413.84,127.07 ; J8.A5 413.84,124.76 ; J4.10 210.88,168.41 ; J4.10 209.82,167.35 ; J4.10 208.76,168.41 ; 57.54,127.3 J9.B5 ; J9.B5 58.7,128.45 ; J9.B5 56.38,128.45 ; J10.10 399.35,2.54
  vias: v1(1.26,136.07) v1(1.26,134.8) v1(1.26,133.53) v1(1.26,132.26) v1(1.26,130.99) v1(1.26,129.72) v1(1.26,128.45) v1(1.26,127.18) v1(1.26,125.91) v1(1.26,124.64) v1(1.26,123.24) v1(1.26,121.97) v1(1.26,120.7) v1(1.26,119.43) v1(1.26,118.16) v1(1.26,116.89) v1(1.26,115.62) v1(1.26,113.08) v1(1.26,111.81) v1(1.26,110.54) v1(1.26,109.27) v1(1.26,108) v1(1.26,106.73) v1(1.26,105.46) v1(1.26,104.19) v1(1.26,102.92) v1(1.26,101.65) v1(1.26,100.38) v1(1.26,99.11) v1(1.26,97.84) v1(1.26,96.57) v1(1.26,95.18) v1(1.26,93.91) v1(1.26,92.64) v1(1.26,91.37) v1(1.26,90.1) v1(1.26,88.83) v1(1.26,87.56) v1(1.26,86.29) v1(1.26,85.02) v1(1.26,83.75) v1(1.26,82.48) v1(1.26,81.21) v1(1.26,79.94) v1(1.26,78.67) v1(1.26,77.4) v1(1.26,76) v1(1.26,74.73) v1(1.26,73.46) v1(1.26,72.19) v1(1.26,70.92) v1(1.26,69.65) v1(1.26,68.38) v1(1.26,67.11) v1(1.26,65.84) v1(1.26,64.57) v1(1.26,63.3) v1(1.26,62.03) v1(1.26,60.76) v1(1.26,59.49) v1(1.26,58.22) v1(1.26,56.95) v1(1.26,55.68) v1(1.26,54.41) v1(1.26,53.14) v1(1.26,51.87) v1(1.26,50.6) v1(1.26,49.33) v1(1.26,48.06) v1(1.26,46.79) v1(1.26,45.52) v1(1.26,44.25) v1(1.26,42.98) v1(1.26,41.71) v1(1.26,40.44) v1(1.26,39.17) v1(1.26,37.9) v1(1.26,36.63) v1(1.26,35.36) v1(1.26,34.09) v1(1.26,32.82) v1(1.26,31.55) v1(1.26,30.28) v1(1.26,28.88) v1(1.26,27.61) v1(1.26,26.34) v1(1.26,25.07) v1(1.26,23.8) v1(1.26,22.53) v1(1.26,21.26) v1(1.26,19.99) v1(1.26,18.72) v1(1.26,17.45) v1(1.26,16.18) v1(1.26,14.91) v1(1.26,13.64) v1(1.26,12.37) v1(1.26,11.1) v1(1.26,9.83) v1(1.26,8.56) v1(1.26,7.29) v1(1.26,6.02) v1(1.26,4.75) v1(1.26,3.48) v1(1.26,2.21) v1(2.4,1.32) v1(3.67,1.32) v1(4.94,1.32) v1(6.21,1.32) v1(7.48,1.32) v1(8.75,1.32) v1(11.29,1.32) v1(12.56,1.32) v1(12.82,98.86) v1(12.94,105.46) v1(12.94,91.11) v1(13.83,1.32) v1(15.1,1.32) v1(15.36,24.31) v1(16.37,1.32) v1(17.64,1.32) v1(18.91,1.32) v1(20.18,1.32) v1(21.45,1.32) v1(22.72,1.32) v1(23.99,1.32) v1(25.26,13.77) v1(25.26,1.32) v1(25.52,24.31) v1(26.53,1.32) v1(27.8,1.32) v1(29.07,1.32) v1(30.34,1.32) v1(31.61,1.32) v1(33.01,1.32) v1(34.03,74.09) v1(34.15,79.17) v1(34.28,1.32) v1(35.42,13.77) v1(35.55,1.32) v1(35.68,24.31) v1(36.69,104.57) v1(36.82,99.75) v1(36.82,1.32) v1(38.09,1.32) v1(39.36,1.32) v1(40.63,1.32) v1(41.9,1.32) v1(43.17,1.32) v1(44.44,1.32) v1(45.58,13.64) v1(45.71,1.32) v1(45.84,24.18) v1(46.98,1.32) v1(48.25,1.32) v1(49.52,1.32) v1(50.28,96.7) v1(50.79,1.32) v1(52.06,1.32) v1(53.33,1.32) v1(54.6,1.32) v1(55.36,78.03) v1(55.35,75.23) v1(55.74,13.64) v1(55.87,1.32) v1(56,24.18) v1(57.14,1.32) v1(58.41,1.32) v1(59.68,1.32) v1(60.95,1.32) v1(62.22,1.32) v1(63.49,1.32) v1(64.51,101.91) v1(64.56,98.35) v1(64.76,1.32) v1(65.52,112.07) v1(65.47,107.88) v1(66.03,1.32) v1(67.3,1.32) v1(68.06,96.57) v1(68.06,13.01) v1(68.32,33.58) v1(68.32,23.55) v1(68.57,1.32) v1(69.84,93.65) v1(69.84,1.32) v1(70.48,88.58) v1(70.6,128.45) v1(71.11,1.32) v1(71.82,144.46) v1(72,89.21) v1(72.38,1.32) v1(73.09,144.46) v1(73.65,1.32) v1(74.36,144.46) v1(74.65,102.8) v1(74.92,1.32) v1(75.63,144.46) v1(76.19,1.32) v1(76.9,144.46) v1(77.46,1.32) v1(78.17,144.46) v1(78.22,13.01) v1(78.48,33.58) v1(78.48,23.55) v1(78.73,1.32) v1(79.49,144.96) v1(80,1.32) v1(80.76,144.96) v1(81.27,1.32) v1(82.03,145.6) v1(82.54,1.32) v1(83.3,185.73) v1(83.3,184.46) v1(83.3,183.19) v1(83.3,181.92) v1(83.3,180.65) v1(83.3,179.38) v1(83.3,169.22) v1(83.3,167.82) v1(83.3,166.55) v1(83.3,165.28) v1(83.3,164.01) v1(83.3,162.74) v1(83.3,161.47) v1(83.3,160.2) v1(83.3,158.93) v1(83.3,157.66) v1(83.3,156.39) v1(83.3,155.12) v1(83.3,153.85) v1(83.3,152.58) v1(83.3,151.31) v1(83.3,150.04) v1(83.3,148.77) v1(83.3,147.5) v1(83.3,146.23) v1(83.81,1.32) v1(83.94,178.11) v1(83.94,176.84) v1(83.94,175.57) v1(83.94,174.3) v1(83.94,173.03) v1(83.94,171.76) v1(83.94,170.49) v1(84.7,186.62) v1(85.08,1.32) v1(85.73,133.1) v1(85.97,186.62) v1(86.35,1.32) v1(87.24,186.62) v1(87.24,80.95) v1(87.62,1.32) v1(88.18,87.45) v1(88.38,13.01) v1(88.59,126.85) v1(88.64,33.58) v1(88.64,23.55) v1(88.89,1.32) v1(89.49,140.43) v1(89.5,80.9) v1(89.79,131.6) v1(90.16,1.32) v1(90.29,155.5) v1(91.05,186.62) v1(91.22,104.07) v1(91.22,100.27) v1(91.22,96.47) v1(91.22,92.67) v1(91.43,1.32) v1(92.19,106.67) v1(92.19,102.87) v1(92.19,99.07) v1(92.19,95.27) v1(92.32,186.62) v1(92.7,1.32) v1(93.26,133.66) v1(93.47,104.07) v1(93.47,100.27) v1(93.47,96.47) v1(93.59,186.62) v1(93.97,1.32) v1(94.1,83.11) v1(94.43,159.13) v1(94.44,106.67) v1(94.44,102.87) v1(94.44,99.07) v1(94.72,126.71) v1(94.86,186.62) v1(95.24,1.32) v1(95.83,159.05) v1(96.13,186.62) v1(96.51,1.32) v1(97.02,143.31) v1(97.08,152.02) v1(97.4,186.62) v1(97.78,1.32) v1(98.54,12.88) v1(98.67,152.58) v1(98.67,33.71) v1(98.8,186.62) v1(98.8,23.42) v1(99.05,1.32) v1(100.07,186.62) v1(100.32,1.32) v1(101.34,186.62) v1(101.59,1.32) v1(101.72,128.04) v1(102.61,186.62) v1(102.86,1.32) v1(102.99,170.87) v1(102.99,168.58) v1(102.99,166.3) v1(103.22,151.95) v1(103.22,104.07) v1(103.22,100.27) v1(103.22,96.47) v1(103.22,92.67) v1(103.71,129.28) v1(103.88,186.62) v1(103.88,170.87) v1(103.88,168.58) v1(103.88,166.3) v1(104.08,147.04) v1(104.11,138.7) v1(104.13,1.32) v1(104.19,106.67) v1(104.19,102.87) v1(104.19,99.07) v1(104.19,95.27) v1(105.15,186.62) v1(105.17,135.6) v1(105.4,1.32) v1(105.47,104.07) v1(105.47,100.27) v1(105.47,96.47) v1(105.66,125.2) v1(106.16,127.56) v1(106.42,186.62) v1(106.44,106.67) v1(106.44,99.07) v1(106.42,61.65) v1(106.45,121.92) v1(106.67,72.19) v1(106.67,1.32) v1(107.69,186.62) v1(107.94,1.32) v1(108.08,129.69) v1(108.57,185.09) v1(108.57,133.22) v1(108.7,12.88) v1(108.83,153.47) v1(108.96,186.62) v1(108.96,33.58) v1(108.96,23.42) v1(109.87,126.8) v1(109.97,121.93) v1(110.23,186.62) v1(111.5,186.62) v1(112.77,186.62) v1(112.87,134.84) v1(113.02,1.32) v1(114.04,186.62) v1(114.32,123.58) v1(114.29,1.32) v1(115.31,186.62) v1(115.56,1.32) v1(116.3,126.14) v1(116.58,186.62) v1(116.58,61.65) v1(116.83,72.19) v1(116.83,1.32) v1(117.85,186.62) v1(118.1,130.36) v1(118.1,1.32) v1(118.73,185.09) v1(118.73,174.93) v1(118.86,12.88) v1(119.12,186.62) v1(119.12,33.58) v1(119.12,23.42) v1(119.37,1.32) v1(120.39,186.62) v1(120.64,1.32) v1(121.27,132.77) v1(121.66,186.62) v1(121.91,1.32) v1(122.05,118.11) v1(122.93,186.62) v1(123.18,1.32) v1(123.32,155.07) v1(123.43,118.16) v1(124.2,186.62) v1(124.45,1.32) v1(124.98,128.4) v1(125.47,186.62) v1(125.72,1.32) v1(126.23,159.18) v1(126.74,186.62) v1(126.75,131.7) v1(126.74,61.52) v1(126.99,72.06) v1(126.99,1.32) v1(128.01,186.62) v1(128.26,1.32) v1(128.89,185.09) v1(128.89,174.93) v1(129.02,12.88) v1(129.28,186.62) v1(129.28,33.58) v1(129.28,23.42) v1(129.53,1.32) v1(130.17,122.68) v1(130.55,186.62) v1(130.8,1.32) v1(131.82,186.62) v1(132.09,108.09) v1(132.07,1.32) v1(132.19,106.7) v1(132.88,129.24) v1(133.09,186.62) v1(133.34,1.32) v1(133.66,103.66) v1(134.36,186.62) v1(134.35,152.82) v1(134.61,1.32) v1(135.63,186.62) v1(135.88,1.32) v1(136.9,186.62) v1(137.15,1.32) v1(137.85,107.56) v1(138.17,186.62) v1(138.42,1.32) v1(139.05,185.09) v1(139.05,174.93) v1(139.18,12.88) v1(139.44,186.62) v1(139.44,33.58) v1(139.44,23.42) v1(139.69,1.32) v1(140.71,186.62) v1(140.96,1.32) v1(141.17,139.95) v1(141.98,186.62) v1(142.23,1.32) v1(142.36,110.54) v1(142.61,89.59) v1(143.25,186.62) v1(143.5,1.32) v1(143.64,169.54) v1(143.79,171.7) v1(143.75,146.74) v1(144.52,186.62) v1(144.77,1.32) v1(145.02,141.28) v1(145.79,186.62) v1(145.97,76.66) v1(146.04,1.32) v1(146.29,68.63) v1(146.42,65.28) v1(146.53,127.42) v1(146.93,145.34) v1(147.06,186.62) v1(147.31,1.32) v1(147.57,87.5) v1(147.57,85.85) v1(148.33,186.62) v1(149.21,185.09) v1(149.21,174.93) v1(149.6,186.62) v1(149.6,33.58) v1(149.6,23.42) v1(150.87,186.62) v1(150.95,89.66) v1(152.14,186.62) v1(153.41,186.62) v1(154.02,89.66) v1(154.55,82.6) v1(154.68,186.62) v1(155.95,186.62) v1(156.96,79.17) v1(157.22,186.62) v1(158.49,186.62) v1(158.49,81.84) v1(158.74,1.32) v1(158.99,57.77) v1(159.37,185.09) v1(159.37,174.93) v1(159.63,157.28) v1(159.76,186.62) v1(159.76,33.58) v1(159.76,23.42) v1(160.01,1.32) v1(160.24,83.39) v1(160.24,82.12) v1(160.24,79.58) v1(160.24,78.31) v1(160.26,64.82) v1(161.03,186.62) v1(161.28,1.32) v1(162.3,186.62) v1(162.55,1.32) v1(163.57,186.62) v1(163.82,1.32) v1(164.84,186.62) v1(165.09,1.32) v1(165.22,162.36) v1(165.34,157.15) v1(166.11,186.62) v1(166.36,1.32) v1(166.72,124.88) v1(167.38,186.62) v1(167.36,96.09) v1(167.36,94.82) v1(167.36,92.28) v1(167.36,91.01) v1(167.36,88.47) v1(167.36,87.2) v1(167.37,83.05) v1(167.36,61.8) v1(167.36,60.53) v1(167.63,1.32) v1(167.99,124.87) v1(168.65,186.62) v1(168.9,1.32) v1(169.38,124.83) v1(169.38,123.05) v1(169.53,185.09) v1(169.53,174.93) v1(169.92,186.62) v1(169.92,33.58) v1(169.92,23.42) v1(170.17,1.32) v1(170.93,56.31) v1(171.19,186.62) v1(171.44,1.32) v1(172.2,162.49) v1(172.33,157.28) v1(172.46,186.62) v1(172.71,1.32) v1(173.04,121.34) v1(173.22,125.02) v1(173.73,186.62) v1(173.85,56.31) v1(173.98,1.32) v1(174.74,56.31) v1(175,186.62) v1(175.25,1.32) v1(175.88,99.82) v1(175.88,98.73) v1(175.96,123.98) v1(176.01,121.31) v1(176.27,186.62) v1(176.52,1.32) v1(177.38,101.53) v1(177.41,69.65) v1(177.54,186.62) v1(177.79,1.32) v1(178.39,101.53) v1(178.81,186.62) v1(178.93,162.49) v1(179.06,157.28) v1(179.06,1.32) v1(179.69,185.35) v1(179.69,175.19) v1(179.82,131.88) v1(180.08,186.62) v1(180.08,33.58) v1(180.08,23.42) v1(180.33,1.32) v1(180.46,106.1) v1(180.46,101.65) v1(180.46,96.57) v1(180.46,91.49) v1(180.46,86.41) v1(180.46,81.33) v1(180.46,76.25) v1(181.35,186.62) v1(181.6,1.32) v1(181.98,140.77) v1(182.62,186.62) v1(182.87,1.32) v1(183.89,186.62) v1(184.14,1.32) v1(185.41,1.32) v1(186.68,1.32) v1(187.7,186.62) v1(187.95,1.32) v1(188.97,186.62) v1(189.22,1.32) v1(189.85,185.35) v1(189.85,175.19) v1(190.24,186.62) v1(190.49,1.32) v1(191.51,186.62) v1(191.76,1.32) v1(192.27,23.42) v1(192.39,34.09) v1(192.39,13.77) v1(192.65,140.77) v1(192.78,186.62) v1(193.03,1.32) v1(194.05,186.62) v1(194.3,1.32) v1(195.32,186.62) v1(195.57,1.32) v1(196.33,156.39) v1(196.59,186.62) v1(196.59,159.69) v1(196.84,1.32) v1(197.86,186.62) v1(198.11,1.32) v1(199.13,186.62) v1(199.38,1.32) v1(199.51,130.61) v1(199.51,120.45) v1(200.01,185.35) v1(200.01,175.19) v1(200.4,186.62) v1(200.65,1.32) v1(201.67,186.62) v1(201.92,1.32) v1(202.05,140.77) v1(202.55,105.21) v1(202.55,95.05) v1(202.55,84.89) v1(202.55,74.73) v1(202.55,64.57) v1(202.55,44.25) v1(202.55,34.09) v1(202.55,24.06) v1(202.55,13.77) v1(202.94,186.62) v1(203.19,1.32) v1(204.21,186.62) v1(204.46,1.32) v1(205.48,186.62) v1(205.73,1.32) v1(206.54,161.67) v1(206.75,186.62) v1(207,1.32) v1(208.02,186.62) v1(208.27,1.32) v1(209.29,186.62) v1(209.54,1.32) v1(210.17,185.35) v1(210.17,175.19) v1(210.17,140.77) v1(210.17,130.61) v1(210.17,120.45) v1(210.56,186.62) v1(210.64,161.42) v1(210.81,1.32) v1(211.83,186.62) v1(212.08,1.32) v1(212.33,156.39) v1(212.59,159.06) v1(212.71,105.21) v1(212.71,95.05) v1(212.71,84.89) v1(212.71,74.73) v1(212.71,54.41) v1(212.71,44.25) v1(212.71,34.09) v1(212.71,24.06) v1(212.71,13.77) v1(213.1,186.62) v1(213.35,1.32) v1(214.37,186.62) v1(214.62,1.32) v1(215.64,186.62) v1(215.89,1.32) v1(216.91,186.62) v1(217.16,1.32) v1(218.18,186.62) v1(218.43,1.32) v1(218.94,158.93) v1(219.45,186.62) v1(219.7,1.32) v1(220.33,185.35) v1(220.33,175.19) v1(220.33,140.77) v1(220.33,130.61) v1(220.33,120.45) v1(220.72,186.62) v1(220.72,151.06) v1(220.97,1.32) v1(221.99,186.62) v1(222.24,1.32) v1(222.87,105.21) v1(222.87,95.05) v1(222.87,84.89) v1(222.87,64.57) v1(222.87,54.41) v1(222.87,44.25) v1(222.87,34.09) v1(222.87,24.06) v1(222.87,13.77) v1(223.26,186.62) v1(223.51,1.32) v1(224.53,186.62) v1(224.78,1.32) v1(225.8,186.62) v1(226.05,1.32) v1(227.07,186.62) v1(227.32,1.32) v1(228.34,186.62) v1(228.59,1.32) v1(229.61,186.62) v1(229.86,1.32) v1(230.49,185.35) v1(230.49,175.19) v1(230.49,140.77) v1(230.49,130.61) v1(230.49,120.45) v1(230.88,186.62) v1(230.88,151.06) v1(231.13,1.32) v1(232.15,186.62) v1(232.4,1.32) v1(232.91,34.22) v1(233.03,105.21) v1(233.03,95.05) v1(233.03,74.73) v1(233.03,64.57) v1(233.03,54.41) v1(233.03,44.25) v1(233.03,23.93) v1(233.03,13.77) v1(233.42,186.62) v1(233.67,1.32) v1(234.69,186.62) v1(234.94,1.32) v1(235.96,186.62) v1(236.21,1.32) v1(237.23,186.62) v1(237.48,1.32) v1(238.5,186.62) v1(238.75,1.32) v1(239.77,186.62) v1(240.02,1.32) v1(240.65,185.35) v1(240.65,175.19) v1(240.65,140.77) v1(240.65,130.61) v1(241.04,186.62) v1(241.04,151.06) v1(241.29,1.32) v1(242.31,186.62) v1(242.56,1.32) v1(242.94,44.38) v1(243.19,105.21) v1(243.19,84.89) v1(243.19,74.73) v1(243.19,64.57) v1(243.19,54.41) v1(243.19,34.09) v1(243.19,23.93) v1(243.19,13.77) v1(243.58,186.62) v1(243.83,1.32) v1(245.1,1.32) v1(246.12,186.62) v1(246.37,1.32) v1(247.39,186.62) v1(247.64,1.32) v1(248.66,186.62) v1(248.91,1.32) v1(249.67,179.76) v1(249.93,186.62) v1(250.18,1.32) v1(250.81,140.77) v1(250.81,130.61) v1(250.81,120.45) v1(251.2,151.06) v1(251.45,1.32) v1(251.83,160.07) v1(252.34,186.62) v1(252.72,1.32) v1(253.35,105.21) v1(253.35,95.05) v1(253.35,84.89) v1(253.35,74.73) v1(253.35,64.57) v1(253.35,54.41) v1(253.35,44.25) v1(253.35,34.09) v1(253.35,23.93) v1(253.35,13.77) v1(253.61,186.62) v1(253.61,184.33) v1(253.61,174.17) v1(253.99,1.32) v1(254.88,186.62) v1(255.26,1.32) v1(256.15,186.62) v1(256.53,1.32) v1(257.42,186.62) v1(257.8,1.32) v1(258.69,186.62) v1(259.07,1.32) v1(259.96,186.62) v1(260.34,1.32) v1(260.97,140.77) v1(260.97,130.61) v1(260.97,120.45) v1(261.23,186.62) v1(261.36,151.06) v1(261.61,1.32) v1(261.99,160.07) v1(262.63,186.62) v1(262.88,1.32) v1(263.26,64.7) v1(263.51,105.21) v1(263.51,95.05) v1(263.51,84.89) v1(263.51,74.73) v1(263.51,54.41) v1(263.51,44.25) v1(263.51,34.09) v1(263.51,23.93) v1(263.51,13.77) v1(263.77,184.33) v1(263.77,174.17) v1(263.9,186.62) v1(264.15,1.32) v1(265.17,186.62) v1(265.42,1.32) v1(266.44,186.62) v1(266.69,1.32) v1(267.71,186.62) v1(267.96,1.32) v1(268.98,186.62) v1(269.23,1.32) v1(270.25,186.62) v1(270.5,1.32) v1(271.13,140.77) v1(271.13,130.61) v1(271.52,186.62) v1(271.52,151.06) v1(271.77,1.32) v1(272.15,160.07) v1(272.79,186.62) v1(273.04,1.32) v1(273.67,105.21) v1(273.67,95.05) v1(273.67,84.89) v1(273.67,64.57) v1(273.67,54.41) v1(273.67,44.25) v1(273.67,34.09) v1(273.67,23.93) v1(273.67,13.77) v1(273.93,184.33) v1(273.93,174.17) v1(274.06,186.62) v1(274.31,1.32) v1(274.56,74.86) v1(275.33,186.62) v1(275.58,1.32) v1(276.6,186.62) v1(276.85,1.32) v1(277.87,186.62) v1(278.12,1.32) v1(279.14,186.62) v1(279.39,1.32) v1(280.41,186.62) v1(280.66,1.32) v1(281.29,140.77) v1(281.29,130.61) v1(281.29,120.45) v1(281.68,186.62) v1(281.68,151.06) v1(281.93,1.32) v1(282.31,160.07) v1(282.95,186.62) v1(283.2,1.32) v1(283.83,105.21) v1(283.83,95.05) v1(283.83,74.73) v1(283.83,64.57) v1(283.83,44.25) v1(283.83,34.09) v1(283.83,23.93) v1(283.83,13.77) v1(283.96,84.89) v1(284.09,184.33) v1(284.09,174.17) v1(284.22,186.62) v1(285.49,186.62) v1(286.76,186.62) v1(288.03,186.62) v1(289.3,186.62) v1(290.57,186.62) v1(291.45,140.77) v1(291.45,130.61) v1(291.84,186.62) v1(293.11,186.62) v1(293.36,172.39) v1(293.36,170.11) v1(293.36,167.82) v1(293.36,1.32) v1(293.99,105.21) v1(293.99,84.89) v1(293.99,74.73) v1(293.99,64.57) v1(293.99,54.41) v1(293.99,44.25) v1(293.99,34.09) v1(293.99,23.93) v1(293.99,13.77) v1(294.25,184.33) v1(294.25,174.17) v1(294.25,172.39) v1(294.25,170.11) v1(294.25,167.82) v1(294.38,186.62) v1(294.63,1.32) v1(295.65,186.62) v1(295.9,1.32) v1(296.92,186.62) v1(297.17,1.32) v1(298.19,186.62) v1(298.44,1.32) v1(299.46,186.62) v1(299.71,1.32) v1(300.73,186.62) v1(300.98,1.32) v1(301.61,150.93) v1(301.61,140.77) v1(301.61,130.61) v1(301.61,120.45) v1(302,186.62) v1(302.25,1.32) v1(303.27,186.62) v1(303.52,1.32) v1(304.15,95.05) v1(304.15,84.89) v1(304.15,74.73) v1(304.15,64.57) v1(304.15,54.41) v1(304.15,44.25) v1(304.15,34.09) v1(304.15,23.93) v1(304.15,13.77) v1(304.41,184.33) v1(304.54,186.62) v1(304.79,1.32) v1(305.81,186.62) v1(305.93,156.14) v1(306.06,1.32) v1(307.08,186.62) v1(307.33,1.32) v1(308.35,186.62) v1(308.6,1.32) v1(309.62,186.62) v1(309.87,1.32) v1(310.89,186.62) v1(311.14,1.32) v1(311.77,150.93) v1(311.77,140.77) v1(311.77,130.61) v1(311.77,120.45) v1(312.16,186.62) v1(312.41,1.32) v1(313.43,186.62) v1(313.68,1.32) v1(314.31,105.21) v1(314.31,84.89) v1(314.31,74.73) v1(314.31,64.57) v1(314.31,54.41) v1(314.31,44.25) v1(314.31,34.09) v1(314.31,23.93) v1(314.31,13.77) v1(314.57,184.33) v1(314.57,174.17) v1(314.7,186.62) v1(314.95,1.32) v1(315.97,186.62) v1(316.22,1.32) v1(317.24,186.62) v1(317.49,1.32) v1(318.51,186.62) v1(318.76,1.32) v1(319.9,186.62) v1(320.03,1.32) v1(321.17,186.62) v1(321.3,1.32) v1(321.81,150.93) v1(321.93,140.77) v1(321.93,130.61) v1(321.93,120.45) v1(322.44,186.62) v1(322.57,1.32) v1(323.71,186.62) v1(323.84,1.32) v1(324.35,33.84) v1(324.35,23.68) v1(324.47,105.21) v1(324.47,95.05) v1(324.47,84.89) v1(324.47,74.73) v1(324.47,64.57) v1(324.47,54.41) v1(324.47,44.25) v1(324.47,13.77) v1(324.73,184.33) v1(324.73,174.17) v1(324.98,186.62) v1(325.11,1.32) v1(326.25,186.62) v1(326.38,1.32) v1(327.52,186.62) v1(327.65,1.32) v1(328.79,186.62) v1(328.92,1.32) v1(330.06,186.62) v1(330.19,1.32) v1(331.21,186.62) v1(331.46,1.32) v1(332.09,150.93) v1(332.09,140.77) v1(332.09,130.61) v1(332.09,120.45) v1(332.48,186.62) v1(332.73,1.32) v1(333.75,186.62) v1(334,1.32) v1(334.51,33.84) v1(334.51,23.68) v1(334.63,105.21) v1(334.63,95.05) v1(334.63,84.89) v1(334.63,74.73) v1(334.63,64.57) v1(334.63,54.41) v1(334.63,44.25) v1(334.63,13.77) v1(335.27,1.32) v1(336.29,186.62) v1(336.54,1.32) v1(337.56,186.62) v1(337.81,1.32) v1(338.83,186.62) v1(340.1,186.62) v1(341.37,186.62) v1(342.25,150.93) v1(342.25,140.77) v1(342.25,130.61) v1(342.64,186.62) v1(343.4,54.66) v1(343.52,64.7) v1(343.91,186.62) v1(344.79,105.21) v1(344.79,74.73) v1(344.79,44.25) v1(344.79,34.09) v1(344.79,13.77) v1(345.18,186.62) v1(346.13,181.19) v1(346.13,179.92) v1(346.13,178.65) v1(346.13,177.38) v1(346.13,176.11) v1(346.13,174.84) v1(346.13,173.57) v1(346.32,155.76) v1(346.32,154.49) v1(346.32,153.22) v1(346.32,151.95) v1(346.32,150.68) v1(346.32,149.41) v1(346.32,148.14) v1(346.32,146.87) v1(346.45,186.49) v1(346.45,184.97) v1(346.45,183.7) v1(346.45,182.43) v1(346.45,172.27) v1(346.45,171) v1(346.45,169.73) v1(346.45,168.46) v1(346.45,167.19) v1(346.45,165.92) v1(346.83,145.72) v1(347.46,144.71) v1(347.97,1.32) v1(348.73,144.71) v1(349.24,1.32) v1(349.87,144.71) v1(350.51,1.32) v1(351.14,144.45) v1(351.41,54.36) v1(351.78,1.32) v1(352.41,144.45) v1(352.41,140.77) v1(352.41,130.61) v1(353.05,1.32) v1(353.68,144.45) v1(354.07,44.12) v1(354.32,1.32) v1(354.95,144.45) v1(354.95,95.05) v1(354.95,84.89) v1(354.95,74.73) v1(354.95,64.57) v1(354.95,34.09) v1(354.95,23.93) v1(354.95,13.77) v1(355.59,1.32) v1(356.22,144.45) v1(356.86,1.32) v1(357.49,144.45) v1(358.13,1.32) v1(358.76,144.45) v1(358.76,143.31) v1(358.76,142.04) v1(358.76,136.19) v1(358.76,134.92) v1(358.76,133.65) v1(358.76,132.38) v1(358.76,131.11) v1(358.76,129.97) v1(359.4,1.32) v1(360.67,1.32) v1(361.94,1.32) v1(363.21,1.32) v1(364.48,1.32) v1(365.11,95.05) v1(365.11,84.89) v1(365.11,74.73) v1(365.11,64.57) v1(365.11,54.41) v1(365.11,13.77) v1(365.75,1.32) v1(367.02,1.32) v1(368.29,1.32) v1(369.56,1.32) v1(370.83,1.32) v1(372.1,1.32) v1(373.24,44) v1(373.37,1.32) v1(374.64,1.32) v1(375.15,74.73) v1(375.15,64.57) v1(375.15,54.41) v1(375.27,95.05) v1(375.27,84.89) v1(375.27,13.77) v1(375.91,1.32) v1(377.18,1.32) v1(378.45,1.32) v1(379.72,1.32) v1(380.99,1.32) v1(381.13,30.73) v1(382.26,1.32) v1(383.28,44) v1(383.53,1.32) v1(384.8,1.32) v1(385.43,95.05) v1(385.43,84.89) v1(385.43,64.57) v1(386.07,1.32) v1(387.34,1.32) v1(388.61,1.32) v1(389.88,1.32) v1(390.01,51.11) v1(390.01,49.96) v1(391.15,1.32) v1(392.42,1.32) v1(392.8,51.11) v1(392.8,49.96) v1(393.56,23.29) v1(393.69,1.32) v1(394.2,22.41) v1(394.2,21.52) v1(394.96,1.32) v1(395.21,21.57) v1(395.59,95.05) v1(395.59,84.89) v1(395.59,74.73) v1(395.59,64.57) v1(396.23,1.32) v1(397.5,1.32) v1(398.77,1.32) v1(399.4,29.9) v1(400.04,29.11) v1(400.04,1.32) v1(400.55,29.9) v1(400.55,28.37) v1(401.31,1.32) v1(402.58,1.32) v1(403.85,1.32) v1(405.12,1.32) v1(405.75,95.05) v1(405.75,84.89) v1(405.75,74.73) v1(405.75,64.57) v1(406.14,46.79) v1(406.39,1.32) v1(407.15,48.31) v1(407.15,46.79) v1(407.15,45.01) v1(407.66,1.32) v1(408.93,1.32) v1(410.2,1.32) v1(411.47,1.32) v1(412.74,1.32) v1(414.01,1.32) v1(415.28,1.32) v1(415.91,95.05) v1(415.91,64.57) v1(416.42,34.85) v1(416.42,24.69) v1(416.55,13.64) v1(416.55,1.32) v1(417.82,1.32) v1(419.09,1.32) v1(421.63,1.32) v1(422.9,1.32) v1(424.17,1.32) v1(425.44,1.32) v1(426.07,95.05) v1(426.07,84.89) v1(426.07,74.73) v1(426.07,64.57) v1(426.58,34.85) v1(426.58,24.69) v1(426.71,13.64) v1(426.71,1.32) v1(427.98,1.32) v1(428.61,109.78) v1(428.61,108.51) v1(428.61,107.24) v1(428.61,105.97) v1(428.61,104.7) v1(428.61,103.43) v1(428.61,102.16) v1(428.61,100.89) v1(428.61,99.62) v1(428.61,98.35) v1(428.61,97.08) v1(428.61,95.81) v1(428.61,94.54) v1(428.61,93.27) v1(428.61,92) v1(428.61,90.73) v1(428.61,89.46) v1(428.61,88.06) v1(428.61,86.79) v1(428.61,85.52) v1(428.61,84.25) v1(428.61,82.98) v1(428.61,81.71) v1(428.61,80.44) v1(428.61,79.17) v1(428.61,77.9) v1(428.61,76.63) v1(428.61,75.36) v1(428.61,74.09) v1(428.61,72.82) v1(428.61,71.55) v1(428.61,70.28) v1(428.61,69.01) v1(428.61,67.74) v1(428.61,66.47) v1(428.61,65.2) v1(428.61,63.93) v1(428.61,62.66) v1(428.61,61.39) v1(428.61,60.12) v1(428.61,58.85) v1(428.61,57.58) v1(428.61,56.31) v1(428.61,55.04) v1(428.61,53.77) v1(428.61,52.5) v1(428.61,51.23) v1(428.61,49.96) v1(428.61,48.69) v1(428.61,47.42) v1(428.61,46.15) v1(428.61,44.88) v1(428.61,43.61) v1(428.61,42.34) v1(428.61,41.07) v1(428.61,39.8) v1(428.61,38.53) v1(428.61,37.26) v1(428.61,35.99) v1(428.61,34.72) v1(428.61,33.45) v1(428.61,32.18) v1(428.61,30.91) v1(428.61,29.64) v1(428.61,28.37) v1(428.61,27.1) v1(428.61,25.83) v1(428.61,24.56) v1(428.61,23.29) v1(428.61,22.02) v1(428.61,20.75) v1(428.61,19.48) v1(428.61,18.21) v1(428.61,16.94) v1(428.61,15.67) v1(428.61,14.4) v1(428.61,13.13) v1(428.61,11.86) v1(428.61,10.59) v1(428.61,9.32) v1(428.61,8.05) v1(428.61,6.78) v1(428.61,5.51) v1(428.61,4.24) v1(428.61,2.97) v1(428.74,136.07) v1(428.74,134.8) v1(428.74,133.53) v1(428.74,132.26) v1(428.74,130.99) v1(428.74,129.72) v1(428.74,128.45) v1(428.74,127.18) v1(428.74,125.91) v1(428.74,124.64) v1(428.74,123.37) v1(428.74,122.1) v1(428.74,120.83) v1(428.74,119.56) v1(428.74,118.29) v1(428.74,117.02) v1(428.74,115.75) v3(17.78,52.96) v3(56.39,52.2) v3(79.25,127) v3(112.01,124.97) v3(114.55,162.81) v3(122.17,143.38) v3(129.92,98.81) v3(130.94,68.45) v3(152.02,43.81) v3(152.53,71.25) v3(180.85,65.28) v3(208.92,162.56) v3(259.97,58.67) v3(262.26,118.11) v3(307.59,162.43) v3(334.77,116.71) v3(335.03,57.66) v3(363.47,20.95) v3(364.36,48.64) v3(389.89,10.03) v3(391.41,10.03) v3(392.94,10.03) v3(394.34,10.03) v3(395.86,10.03) v3(397.26,10.03) v3(398.65,10.03) v3(411.73,102.87) v3(413.26,102.87) v3(414.78,102.87) v3(416.18,102.87) v3(417.7,102.87) v3(419.1,102.87) v3(419.86,28.96) v3(420.5,102.87) v3(420.5,74.55) v4(9.26,40.82) v4(9.26,39.04) v4(9.26,37.14) v4(9.26,35.23) v4(9.26,33.33) v4(9.26,31.68) v4(11.29,40.82) v4(11.29,39.04) v4(11.29,37.14) v4(11.29,35.23) v4(11.29,33.33) v4(11.29,31.68) v4(13.45,40.82) v4(13.45,39.04) v4(13.45,37.14) v4(13.45,35.23) v4(13.45,33.33) v4(13.45,31.68) v4(15.61,40.82) v4(15.61,39.04) v4(15.61,37.14) v4(15.61,35.23) v4(15.61,33.33) v4(15.61,31.68) v4(17.64,40.82) v4(17.64,39.04) v4(17.64,37.14) v4(17.64,35.23) v4(17.64,33.33) v4(17.64,31.68) v4(19.55,40.82) v4(19.55,39.04) v4(19.55,37.14) v4(19.55,35.23) v4(19.55,33.33) v4(19.55,31.68) v4(21.45,35.23) v4(21.45,33.33) v4(21.45,31.68) v4(23.34,120.88) v4(23.34,119.23) v4(23.29,115.54) v4(23.29,113.76) v4(23.36,40.69) v4(23.36,38.92) v4(23.36,37.01) v4(23.36,35.11) v4(23.36,33.33) v4(23.36,31.68) v4(47.74,40.82) v4(47.74,39.04) v4(47.74,37.14) v4(47.74,35.23) v4(47.74,33.33) v4(47.74,31.68) v4(49.77,40.82) v4(49.77,39.04) v4(49.77,37.14) v4(49.77,35.23) v4(49.77,33.33) v4(49.77,31.68) v4(51.93,40.82) v4(51.93,39.04) v4(51.93,37.14) v4(51.93,35.23) v4(51.93,33.33) v4(51.93,31.68) v4(54.09,40.82) v4(54.09,39.04) v4(54.09,37.14) v4(54.09,35.23) v4(54.09,33.33) v4(54.09,31.68) v4(56.12,40.82) v4(56.12,39.04) v4(56.12,37.14) v4(56.12,35.23) v4(56.12,33.33) v4(56.12,31.68) v4(58.03,40.82) v4(58.03,39.04) v4(58.03,37.14) v4(58.03,35.23) v4(58.03,33.33) v4(58.03,31.68) v4(59.93,35.23) v4(59.93,33.33) v4(59.93,31.68) v4(61.84,40.69) v4(61.84,38.92) v4(61.84,37.01) v4(61.84,35.11) v4(61.84,33.33) v4(61.84,31.68) v4(84.8,122.71) v4(84.83,121.47) v4(85.05,129.75) v4(85.81,124.67) v4(86.3,129.74) v4(86.32,122.71) v4(86.35,121.47) v4(87.06,124.66) v4(87.62,129.75) v4(88.1,122.71) v4(88.13,121.47) v4(88.38,124.67) v4(373.18,115.8) v4(373.18,113.89) v4(373.18,111.86) v4(376.48,115.8) v4(376.48,113.89) v4(376.48,111.86) v4(379.27,119.86) v4(379.27,117.96) v4(379.27,115.8) v4(379.27,113.89) v4(379.27,111.86) v4(381.38,24.28) v4(381.62,20.12) v4(382.27,23.19) v4(382.77,18.85) v4(410.2,123.5) v4(411.78,123.54) v4(411.78,122.27) v4(411.78,120.88) v4(411.78,116.43) v4(411.78,115.03) v4(411.78,113.38) v4(411.78,111.99) v4(411.78,110.34) v4(411.78,106.91) v4(411.78,104.75) v4(413.12,118.42) v4(413.31,123.54) v4(413.31,122.27) v4(413.31,120.88) v4(413.31,116.43) v4(413.31,115.03) v4(413.31,113.38) v4(413.31,111.99) v4(413.31,110.34) v4(413.27,108.64) v4(413.31,106.91) v4(413.31,104.75) v4(414.52,118.42) v4(414.52,108.64) v4(414.55,123.54) v4(414.55,122.27) v4(414.55,120.88) v4(414.55,116.43) v4(414.55,115.03) v4(414.55,113.38) v4(414.55,111.99) v4(414.55,110.34) v4(414.55,106.91) v4(414.55,104.75) v4(415.81,123.5) v4(415.81,122.23) v4(415.81,120.83) v4(415.81,116.39) v4(415.81,114.99) v4(415.81,113.34) v4(415.81,111.94) v4(415.81,110.29) v4(415.78,108.59) v4(415.81,106.86) v4(415.81,104.7) v4(415.91,118.42) v4(417.02,108.59) v4(417.06,123.5) v4(417.06,122.23) v4(417.06,120.83) v4(417.06,116.39) v4(417.06,114.99) v4(417.06,113.34) v4(417.06,111.94) v4(417.06,110.29) v4(417.06,106.86) v4(417.06,104.7) v4(418.33,123.5) v4(418.33,122.23) v4(418.33,120.83) v4(418.33,116.39) v4(418.33,114.99) v4(418.33,113.34) v4(418.33,111.94) v4(418.33,110.29) v4(418.29,108.59) v4(418.33,106.86) v4(418.33,104.7)
